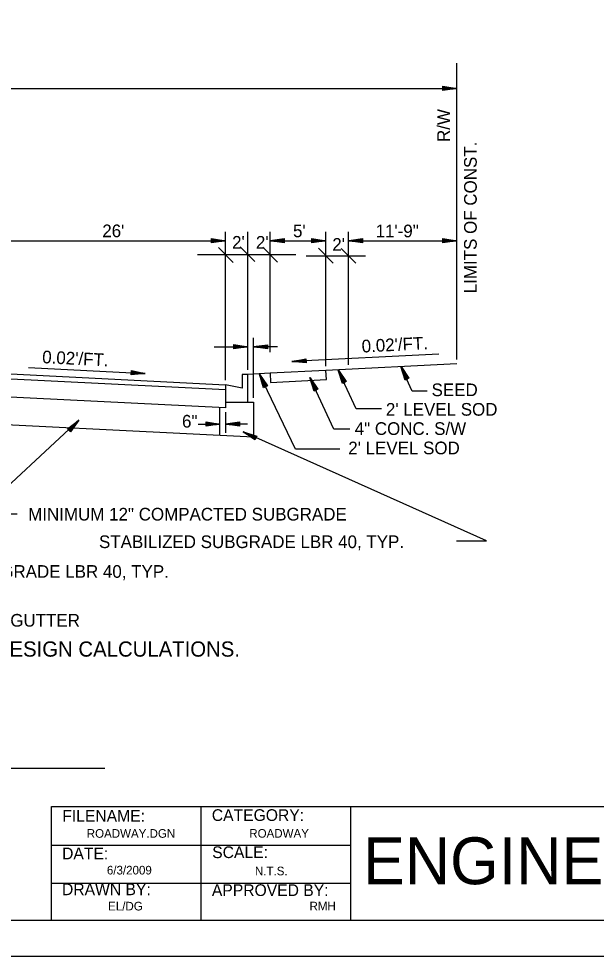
# Model space of a CAD drawing. Extents: x 29.7 to 46.4, y -39.2 to -28.2.
# Drawn here: x 36.79 to 40.59, y -39.2 to -33.04 of the extents above; entities that cross this region are included whole.
import ezdxf

# ---------------------------------------------------------------- set-up
doc = ezdxf.new("R2010")
doc.units = 0
for name, color, linetype in [('Level 1', 7, 'Continuous'), ('Level 4', 7, 'Continuous'), ('Level 60', 7, 'Continuous'), ('Level 62', 7, 'Continuous'), ('Level 8', 7, 'Continuous'), ('Level 9', 7, 'Continuous')]:
    doc.layers.add(name, color=color, linetype=linetype)

msp = doc.modelspace()

# ---------------------------------------------------------------- linework, layer by layer
at = {"layer": 'Level 4'}
msp.add_line((37.3605, -37.9659), (32.8081, -37.9659), dxfattribs=at)
at = {"layer": 'Level 60'}
for p, q in [((37.0112, -38.965), (37.0112, -38.2154)), ((37.9948, -38.9652), (37.9948, -38.2154)), ((38.9784, -38.9651), (38.9784, -38.2154)), ((38.9784, -38.9651), (38.9784, -38.514))]:
    msp.add_line(p, q, dxfattribs=at)
for points in [[(29.7027, -39.1993), (46.0327, -39.1993), (46.0327, -28.1926), (29.7027, -28.1926)], [(30.3565, -28.4094), (45.7818, -28.4094), (45.7818, -38.965), (30.3565, -38.965)]]:
    msp.add_lwpolyline(points, close=True, dxfattribs=at)
for points in [[(37.0112, -38.2154), (41.923, -38.2154)], [(37.0112, -38.4692), (38.9784, -38.4692)], [(37.0112, -38.7191), (38.9784, -38.7191)]]:
    msp.add_lwpolyline(points, dxfattribs=at)
at = {"layer": 'Level 8'}
for p, q in [((39.6765, -35.2762), (39.6765, -33.3281)), ((30.8765, -33.4948), (39.6765, -33.4948)), ((38.1548, -35.4128), (38.1548, -34.4376)), ((38.3015, -35.345), (38.3015, -34.4376)), ((38.4481, -35.2269), (38.4481, -34.4376)), ((38.8148, -35.3193), (38.8148, -34.4376)), ((38.9645, -35.3118), (38.9645, -34.4376)), ((36.2481, -34.4953), (38.1548, -34.4953)), ((38.4481, -34.4953), (38.8148, -34.4953)), ((38.9645, -34.4953), (39.6765, -34.4953)), ((38.1086, -34.5396), (38.205, -34.6376)), ((38.2507, -34.5346), (38.347, -34.6326)), ((38.4003, -34.5383), (38.4966, -34.6363)), ((38.7661, -34.5446), (38.8625, -34.6426)), ((38.9145, -34.5459), (39.0108, -34.6439)), ((37.9704, -34.5859), (38.3015, -34.5859)), ((38.3015, -34.5859), (38.6166, -34.5859)), ((38.6845, -34.5947), (39.0743, -34.5947)), ((38.0811, -35.1924), (38.3015, -35.1924)), ((38.3381, -35.5283), (38.3381, -35.1346)), ((38.4973, -35.1924), (38.3381, -35.1924)), ((39.5577, -35.2407), (38.5918, -35.289)), ((39.6765, -35.3051), (38.8148, -35.3482)), ((36.1198, -35.3399), (38.1548, -35.4417)), ((36.2481, -35.3776), (38.1548, -35.4729)), ((36.8596, -35.3296), (37.6271, -35.368)), ((38.4481, -35.3665), (38.3015, -35.3739)), ((38.1181, -35.7758), (38.1181, -35.5922)), ((38.1548, -35.6229), (38.1548, -35.7584)), ((37.9738, -35.7007), (38.1181, -35.7007)), ((38.2991, -35.7007), (38.1548, -35.7007))]:
    msp.add_line(p, q, dxfattribs=at)
for points in [[(38.3015, -35.3739), (38.2648, -35.3739), (38.2648, -35.4655), (38.1548, -35.4417), (38.1548, -35.5572), (38.3015, -35.5572), (38.3015, -35.3739)], [(38.9058, -35.8659), (38.6143, -35.8662), (38.378, -35.373)], [(38.8148, -35.3482), (38.4481, -35.3665), (38.4511, -35.4269), (38.8178, -35.4086), (38.8148, -35.3482)], [(39.1806, -35.6014), (39.0148, -35.6014), (38.8959, -35.3458)], [(39.4816, -35.4848), (39.3829, -35.4846), (39.3083, -35.3226)], [(38.9731, -35.7333), (38.867, -35.7333), (38.7097, -35.3956)], [(38.3015, -35.5572), (38.3381, -35.5572), (38.3381, -35.7868), (36.0465, -35.6722), (36.0465, -35.4619), (36.0831, -35.4619)], [(38.1548, -35.5572), (38.1548, -35.594), (36.2481, -35.4987), (36.2481, -35.4619)], [(36.7845, -36.2929), (36.5246, -36.2929), (37.189, -35.6752)], [(39.673, -36.4674), (39.87, -36.4677), (38.2714, -35.7511)]]:
    msp.add_lwpolyline(points, dxfattribs=at)
at = {"layer": 'Level 9'}
for p, q in [((39.5849, -33.5085), (39.5849, -33.4801)), ((39.5849, -33.4801), (39.6763, -33.4951)), ((39.6765, -33.4948), (39.5849, -33.4856)), ((39.5849, -33.4856), (39.5849, -33.4994)), ((39.5849, -33.4948), (39.5849, -33.4902)), ((39.5849, -33.4902), (39.6765, -33.4948)), ((39.5849, -33.5039), (39.6765, -33.4948)), ((39.6765, -33.4948), (39.5849, -33.4948)), ((39.5849, -33.4994), (39.6719, -33.4948)), ((39.676, -33.4954), (39.5849, -33.5085)), ((38.0632, -34.509), (38.0632, -34.4807)), ((38.0632, -34.4807), (38.1546, -34.4956)), ((38.1543, -34.4959), (38.0632, -34.509)), ((38.1548, -34.4953), (38.0633, -34.4862)), ((38.0633, -34.4862), (38.0633, -34.4999)), ((38.0633, -34.4953), (38.0633, -34.4908)), ((38.0633, -34.4908), (38.1548, -34.4953)), ((38.0633, -34.5045), (38.1548, -34.4953)), ((38.1548, -34.4953), (38.0633, -34.4953)), ((38.0633, -34.4999), (38.1502, -34.4953)), ((38.5396, -34.4862), (38.4481, -34.4953)), ((38.4481, -34.4953), (38.5396, -34.4953)), ((38.5396, -34.4999), (38.4481, -34.4953)), ((38.4481, -34.4953), (38.5396, -34.5045)), ((38.5397, -34.51), (38.4483, -34.4951)), ((38.4486, -34.4947), (38.5397, -34.4816)), ((38.5396, -34.4908), (38.4527, -34.4953)), ((38.5396, -34.5045), (38.5396, -34.4908)), ((38.5396, -34.4953), (38.5396, -34.4999)), ((38.5397, -34.4816), (38.5397, -34.51)), ((38.7232, -34.509), (38.7232, -34.4807)), ((38.7232, -34.4807), (38.8146, -34.4956)), ((38.8143, -34.4959), (38.7232, -34.509)), ((38.8148, -34.4953), (38.7233, -34.4862)), ((38.7233, -34.4862), (38.7233, -34.4999)), ((38.7233, -34.4953), (38.7233, -34.4908)), ((38.7233, -34.4908), (38.8148, -34.4953)), ((38.7233, -34.5045), (38.8148, -34.4953)), ((38.8148, -34.4953), (38.7233, -34.4953)), ((38.7233, -34.4999), (38.8102, -34.4953)), ((39.056, -34.4862), (38.9645, -34.4953)), ((38.9645, -34.4953), (39.056, -34.4953)), ((39.056, -34.4999), (38.9645, -34.4953)), ((38.9645, -34.4953), (39.056, -34.5045)), ((39.0561, -34.51), (38.9646, -34.4951)), ((38.9649, -34.4947), (39.0561, -34.4816)), ((39.056, -34.4908), (38.9691, -34.4953)), ((39.056, -34.5045), (39.056, -34.4908)), ((39.056, -34.4953), (39.056, -34.4999)), ((39.0561, -34.4816), (39.0561, -34.51)), ((39.5849, -34.509), (39.5849, -34.4807)), ((39.5849, -34.4807), (39.6763, -34.4956)), ((39.6765, -34.4953), (39.5849, -34.4862)), ((39.5849, -34.4862), (39.5849, -34.4999)), ((39.5849, -34.4953), (39.5849, -34.4908)), ((39.5849, -34.4908), (39.6765, -34.4953)), ((39.5849, -34.5045), (39.6765, -34.4953)), ((39.6765, -34.4953), (39.5849, -34.4953)), ((39.5849, -34.4999), (39.6719, -34.4953)), ((39.676, -34.4959), (39.5849, -34.509)), ((38.2099, -35.2061), (38.2099, -35.1777)), ((38.2099, -35.1777), (38.3013, -35.1926)), ((38.3015, -35.1924), (38.2099, -35.1832)), ((38.2099, -35.1832), (38.2099, -35.1969)), ((38.2099, -35.1924), (38.2099, -35.1878)), ((38.2099, -35.1878), (38.3015, -35.1924)), ((38.2099, -35.2015), (38.3015, -35.1924)), ((38.3015, -35.1924), (38.2099, -35.1924)), ((38.2099, -35.1969), (38.2969, -35.1924)), ((38.4296, -35.1832), (38.3381, -35.1924)), ((38.3381, -35.1924), (38.4296, -35.1924)), ((38.4296, -35.1969), (38.3381, -35.1924)), ((38.3381, -35.1924), (38.4296, -35.2015)), ((38.4297, -35.207), (38.3383, -35.1921)), ((38.3386, -35.1918), (38.4297, -35.1787)), ((38.4296, -35.1878), (38.3427, -35.1924)), ((38.4296, -35.2015), (38.4296, -35.1878)), ((38.4296, -35.1924), (38.4296, -35.1969)), ((38.4297, -35.1787), (38.4297, -35.207)), ((38.301, -35.193), (38.2099, -35.2061)), ((38.6827, -35.2753), (38.5918, -35.289)), ((38.5918, -35.289), (38.6832, -35.2844)), ((38.6834, -35.289), (38.5918, -35.289)), ((38.5918, -35.289), (38.6836, -35.2935)), ((38.684, -35.299), (38.5919, -35.2887)), ((38.5922, -35.2884), (38.6825, -35.2707)), ((38.6829, -35.2798), (38.5963, -35.2887)), ((38.6825, -35.2707), (38.684, -35.299)), ((38.6836, -35.2935), (38.6829, -35.2798)), ((38.6832, -35.2844), (38.6834, -35.289)), ((37.535, -35.3771), (37.5364, -35.3488)), ((37.6266, -35.3685), (37.535, -35.3771)), ((37.5353, -35.3725), (37.6271, -35.368)), ((37.5362, -35.3543), (37.5355, -35.368)), ((37.5355, -35.368), (37.6226, -35.3677)), ((37.5357, -35.3634), (37.536, -35.3588)), ((37.6271, -35.368), (37.5357, -35.3634)), ((37.536, -35.3588), (37.6271, -35.368)), ((37.6271, -35.368), (37.5362, -35.3543)), ((37.5364, -35.3488), (37.627, -35.3682)), ((38.4267, -35.451), (38.378, -35.373)), ((38.378, -35.373), (38.4185, -35.4551)), ((38.4144, -35.4571), (38.378, -35.373)), ((38.378, -35.373), (38.4103, -35.4591)), ((38.4054, -35.4616), (38.3783, -35.373)), ((38.3787, -35.3731), (38.4308, -35.4491)), ((38.4226, -35.453), (38.38, -35.3771)), ((38.9446, -35.4238), (38.8959, -35.3458)), ((38.8959, -35.3458), (38.9364, -35.4278)), ((38.9323, -35.4299), (38.8959, -35.3458)), ((38.8959, -35.3458), (38.9282, -35.4319)), ((38.9233, -35.4344), (38.8962, -35.3458)), ((38.8967, -35.3459), (38.9487, -35.4219)), ((38.9405, -35.4258), (38.8979, -35.3499)), ((39.357, -35.4006), (39.3083, -35.3226)), ((39.3083, -35.3226), (39.3488, -35.4047)), ((39.3447, -35.4067), (39.3083, -35.3226)), ((39.3083, -35.3226), (39.3406, -35.4087)), ((39.3357, -35.4112), (39.3086, -35.3226)), ((39.3091, -35.3228), (39.3611, -35.3987)), ((39.3529, -35.4027), (39.3104, -35.3267)), ((38.7584, -35.4736), (38.7097, -35.3956)), ((38.7097, -35.3956), (38.7502, -35.4777)), ((38.7461, -35.4797), (38.7097, -35.3956)), ((38.7097, -35.3956), (38.742, -35.4817)), ((38.7371, -35.4842), (38.71, -35.3956)), ((38.7104, -35.3958), (38.7625, -35.4717)), ((38.7543, -35.4756), (38.7117, -35.3997)), ((38.9487, -35.4219), (38.9233, -35.4344)), ((38.9282, -35.4319), (38.9405, -35.4258)), ((38.9364, -35.4278), (38.9323, -35.4299)), ((39.3611, -35.3987), (39.3357, -35.4112)), ((39.3406, -35.4087), (39.3529, -35.4027)), ((39.3488, -35.4047), (39.3447, -35.4067)), ((38.4308, -35.4491), (38.4054, -35.4616)), ((38.4103, -35.4591), (38.4226, -35.453)), ((38.4185, -35.4551), (38.4144, -35.4571)), ((38.7625, -35.4717), (38.7371, -35.4842)), ((38.742, -35.4817), (38.7543, -35.4756)), ((38.7502, -35.4777), (38.7461, -35.4797)), ((37.1155, -35.7318), (37.1891, -35.6755)), ((37.189, -35.6752), (37.1195, -35.7355)), ((37.1229, -35.7386), (37.189, -35.6752)), ((37.189, -35.6752), (37.1262, -35.7418)), ((37.1295, -35.7449), (37.1858, -35.6785)), ((37.1329, -35.748), (37.189, -35.6752)), ((37.1891, -35.6759), (37.1361, -35.7512)), ((37.1361, -35.7512), (37.1155, -35.7318)), ((37.1195, -35.7355), (37.1295, -35.7449)), ((37.1262, -35.7418), (37.1229, -35.7386)), ((38.0265, -35.7144), (38.0265, -35.6861)), ((38.0265, -35.6861), (38.118, -35.701)), ((38.1177, -35.7013), (38.0265, -35.7144)), ((38.1181, -35.7007), (38.0266, -35.6916)), ((38.0266, -35.6916), (38.0266, -35.7053)), ((38.0266, -35.7007), (38.0266, -35.6961)), ((38.0266, -35.6961), (38.1181, -35.7007)), ((38.0266, -35.7098), (38.1181, -35.7007)), ((38.1181, -35.7007), (38.0266, -35.7007)), ((38.0266, -35.7053), (38.1135, -35.7007)), ((38.2463, -35.6916), (38.1548, -35.7007)), ((38.1548, -35.7007), (38.2463, -35.7007)), ((38.2463, -35.7053), (38.1548, -35.7007)), ((38.1548, -35.7007), (38.2463, -35.7098)), ((38.2464, -35.7153), (38.1549, -35.7004)), ((38.1553, -35.7001), (38.2464, -35.687)), ((38.2463, -35.6961), (38.1594, -35.7007)), ((38.2463, -35.7098), (38.2463, -35.6961)), ((38.2463, -35.7007), (38.2463, -35.7053)), ((38.2464, -35.687), (38.2464, -35.7153)), ((38.3575, -35.7835), (38.2714, -35.7511)), ((38.2714, -35.7511), (38.3535, -35.7917)), ((38.3514, -35.7958), (38.2714, -35.7511)), ((38.2714, -35.7511), (38.3494, -35.7999)), ((38.347, -35.8048), (38.2717, -35.7509)), ((38.2721, -35.7508), (38.3596, -35.7794)), ((38.3555, -35.7876), (38.2755, -35.7531)), ((38.3596, -35.7794), (38.347, -35.8048)), ((38.3494, -35.7999), (38.3555, -35.7876)), ((38.3535, -35.7917), (38.3514, -35.7958))]:
    msp.add_line(p, q, dxfattribs=at)

# ---------------------------------------------------------------- texts
at = {"layer": 'Level 1'}
msp.add_text('FINAL LAYER THICKNESSES TO BE DETERMINED BY THE ENGINEERS PAVEMENT DESIGN CALCULATIONS.', height=0.1, dxfattribs=at).set_placement((31.2874, -37.2297))
at = {"layer": 'Level 60'}
for s, height, p in [('FILENAME:', 0.07704, (37.0811, -38.3154)), ('CATEGORY:', 0.07704, (38.0646, -38.31)), ('ROADWAY.DGN  ', 0.056725, (37.2422, -38.4203)), ('ENGINEERING STANDARDS MANUAL', 0.308157, (39.0591, -38.7259)), ('DATE:', 0.07704, (37.0799, -38.562)), ('SCALE:', 0.07704, (38.0672, -38.5541)), ('DRAWN BY:', 0.07704, (37.0792, -38.7978)), ('APPROVED BY:', 0.077039, (38.0651, -38.8033)), ('RMH', 0.05673, (38.7072, -38.8979))]:
    msp.add_text(s, height=height, dxfattribs=at).set_placement(p)
at = {"layer": 'Level 62'}
for s, height, p in [('      ROADWAY', 0.056725, (38.1846, -38.4199)), ('6/3/2009', 0.05673, (37.3746, -38.6617)), ('N.T.S.', 0.05673, (38.3481, -38.6673)), ('N.T.S.', 0.05673, (38.3481, -38.6673)), ('EL/DG  ', 0.05673, (37.3827, -38.8983))]:
    msp.add_text(s, height=height, dxfattribs=at).set_placement(p)
at = {"layer": 'Level 8'}
for s, height, rotation, p in [('R/W', 0.08333, 90, (39.6301, -33.8461)), ('LIMITS OF CONST.', 0.083333, 90, (39.8069, -34.8408)), ("0.02'/FT.", 0.08333, 2.86241, (39.0522, -35.2308)), ("0.02'/FT.", 0.08333, 357.13759, (36.9475, -35.3))]:
    msp.add_text(s, height=height, rotation=rotation, dxfattribs=at).set_placement(p)
for s, height, p in [("26'", 0.08333, (37.3442, -34.4722)), ("5'", 0.08333, (38.5987, -34.4722)), ('11\'-9"', 0.08333, (39.1416, -34.4729)), ("2'", 0.08333, (38.1979, -34.5477)), ("2'", 0.08333, (38.3546, -34.5477)), ("2'", 0.08333, (38.8569, -34.5616)), ('SEED', 0.08333, (39.51, -35.5172)), ("2' LEVEL SOD", 0.083333, (39.2095, -35.6456)), ('6"', 0.08333, (37.8685, -35.7238)), ('4" CONC. S/W', 0.083333, (39.0043, -35.772)), ("2' LEVEL SOD", 0.083333, (38.9618, -35.8994)), ('MINIMUM 12" COMPACTED SUBGRADE', 0.083333, (36.8569, -36.3348)), ('STABILIZED SUBGRADE LBR 40, TYP.', 0.083333, (37.3225, -36.516)), ('STABILIZED SUBGRADE LBR 40, TYP.', 0.083333, (35.7755, -36.7114)), ('TYPE "E" CURB & GUTTER', 0.083333, (35.7808, -37.0325))]:
    msp.add_text(s, height=height, dxfattribs=at).set_placement(p)

doc.saveas('drawing.dxf')
